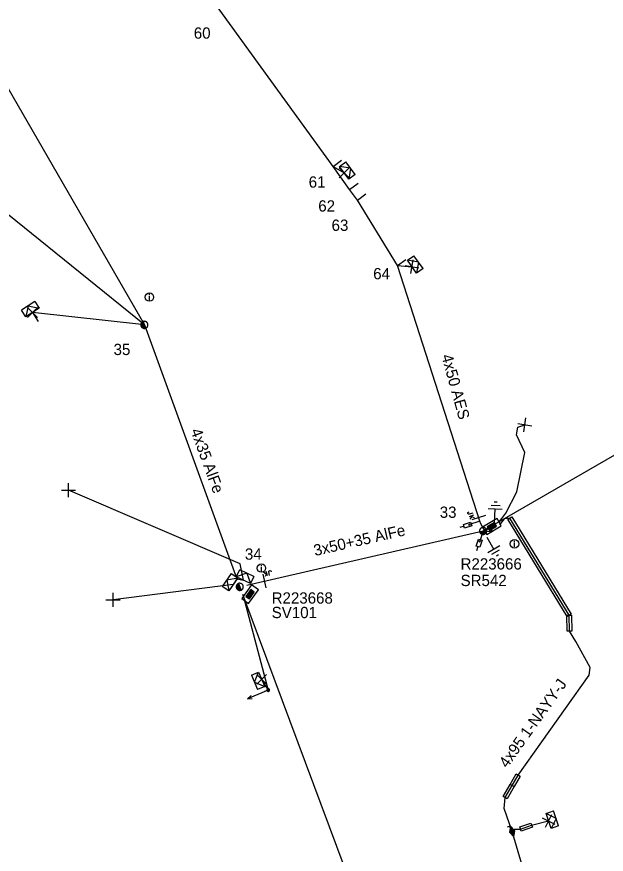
# Model space of a CAD drawing. Extents: x -536149 to -535465, y -1201639 to -1201298.
# Drawn here: x -535581.6 to -535529.3, y -1201567.7 to -1201493.4 of the extents above; entities that cross this region are included whole.
import ezdxf

# ---------------------------------------------------------------- set-up
doc = ezdxf.new("R2010")
doc.units = 0
for name, color, linetype in [('Vrstva 1', 7, 'Continuous'), ('Vrstva 10', 7, 'Continuous'), ('Vrstva 13', 7, 'Continuous'), ('Vrstva 14', 7, 'Continuous'), ('Vrstva 15', 7, 'Continuous'), ('Vrstva 16', 7, 'Continuous'), ('Vrstva 18', 7, 'Continuous'), ('Vrstva 19', 7, 'Continuous'), ('Vrstva 2', 7, 'Continuous'), ('Vrstva 20', 7, 'Continuous'), ('Vrstva 28', 7, 'Continuous'), ('Vrstva 29', 7, 'Continuous'), ('Vrstva 30', 7, 'Continuous'), ('Vrstva 31', 7, 'Continuous'), ('Vrstva 34', 7, 'Continuous'), ('Vrstva 36', 7, 'Continuous'), ('Vrstva 4', 7, 'Continuous'), ('Vrstva 5', 7, 'Continuous'), ('Vrstva 50', 7, 'Continuous'), ('Vrstva 51', 7, 'Continuous'), ('Vrstva 52', 7, 'Continuous'), ('Vrstva 54', 7, 'Continuous'), ('Vrstva 59', 7, 'Continuous'), ('Vrstva 6', 7, 'Continuous'), ('Vrstva 8', 7, 'Continuous'), ('Vrstva 9', 7, 'Continuous')]:
    doc.layers.add(name, color=color, linetype=linetype)

# ---------------------------------------------------------------- blocks, each defined once
blk = doc.blocks.new('NN440')
at = {"layer": 'Vrstva 2'}
for points in [[(0.63, 0), (0.63, 0.06), (0.62, 0.13), (0.6, 0.19), (0.58, 0.25), (0.55, 0.31), (0.51, 0.37), (0.47, 0.42), (0.42, 0.46), (0.37, 0.51), (0.32, 0.54), (0.26, 0.57), (0.2, 0.59), (0.13, 0.61), (0.07, 0.62), (0, 0.63), (-0.06, 0.62), (-0.13, 0.61), (-0.19, 0.59), (-0.26, 0.57), (-0.31, 0.54), (-0.37, 0.51), (-0.42, 0.46), (-0.47, 0.42), (-0.51, 0.37), (-0.54, 0.31), (-0.57, 0.25), (-0.6, 0.19), (-0.62, 0.13), (-0.63, 0.06), (-0.63, 0), (-0.63, -0.07), (-0.62, -0.14), (-0.6, -0.2), (-0.57, -0.26), (-0.54, -0.32), (-0.51, -0.37), (-0.47, -0.43), (-0.42, -0.47), (-0.37, -0.51), (-0.31, -0.55), (-0.26, -0.58), (-0.19, -0.6), (-0.13, -0.62), (-0.06, -0.63), (0, -0.63), (0.07, -0.63), (0.13, -0.62), (0.2, -0.6), (0.26, -0.58), (0.32, -0.55), (0.37, -0.51), (0.42, -0.47), (0.47, -0.43), (0.51, -0.37), (0.55, -0.32), (0.58, -0.26), (0.6, -0.2), (0.62, -0.14), (0.63, -0.07), (0.63, 0)], [(-0.63, 0), (0.63, 0)], [(-0.6, -0.18), (0.57, -0.18)], [(-0.51, -0.32), (0.5, -0.32)], [(-0.37, -0.47), (0.35, -0.47)]]:
    blk.add_lwpolyline(points, dxfattribs=at)
blk = doc.blocks.new('NN560')
at = {"layer": 'Vrstva 2'}
for points in [[(1.999, -0.001), (1.59, 0.141)], [(0, -0.001), (1.999, -0.001)], [(1.999, -0.001), (1.59, -0.134)]]:
    blk.add_lwpolyline(points, dxfattribs=at)
blk = doc.blocks.new('NN840')
at = {"layer": 'Vrstva 15'}
for points in [[(0.003, 0.619), (0.003, -0.631)], [(-0.745, -0.71), (-0.745, -0.66)], [(-0.73, -0.764), (-0.745, -0.71)], [(-0.538, -0.71), (-0.558, -0.764)], [(-0.538, -0.385), (-0.538, -0.71)], [(-0.332, -0.385), (-0.332, -0.798)], [(-0.332, -0.641), (-0.125, -0.385)], [(-0.263, -0.557), (-0.091, -0.798)], [(-0.657, -0.798), (-0.73, -0.764)], [(-0.627, -0.798), (-0.657, -0.798)], [(-0.558, -0.764), (-0.627, -0.798)]]:
    blk.add_lwpolyline(points, dxfattribs=at)
blk = doc.blocks.new('NN770')
at = {"layer": 'Vrstva 10'}
for p, q in [((0.002, 0.187), (0.002, 0.263)), ((0.002, -0.276), (0.002, 0.111))]:
    blk.add_line(p, q, dxfattribs=at)
blk.add_circle((0, -0.008), 0.375, dxfattribs=at)
blk = doc.blocks.new('NN880')
at = {"layer": 'Vrstva 4'}
for points in [[(0.001, 0.248), (-0.499, 0)], [(0.001, 0.185), (-0.373, 0)], [(0.001, 0.122), (-0.247, 0)], [(0.001, 0.059), (-0.125, 0)], [(0.501, 0), (0.001, 0.248)], [(0.375, 0), (0.001, 0.185)], [(0.249, 0), (0.001, 0.122)], [(0.127, 0), (0.001, 0.059)], [(-0.566, -0.13), (-0.436, -0.13)], [(-0.499, 0), (0.001, -0.252)], [(-0.499, -0.13), (-0.499, -0.327)], [(-0.373, 0), (0.001, -0.189)], [(-0.247, 0), (0.001, -0.126)], [(-0.125, 0), (0.001, -0.063)], [(0.001, -0.252), (0.501, 0)], [(0.001, -0.189), (0.375, 0)], [(0.001, -0.126), (0.249, 0)], [(0.001, -0.063), (0.127, 0)]]:
    blk.add_lwpolyline(points, dxfattribs=at)
blk = doc.blocks.new('NN800')
at = {"layer": 'Vrstva 1'}
for points in [[(-0.442, 0.442), (0.442, -0.442)], [(-0.442, -0.442), (0.442, 0.442)]]:
    blk.add_lwpolyline(points, dxfattribs=at)
blk = doc.blocks.new('NN820')
at = {"layer": 'Vrstva 13'}
for points in [[(-0.003, 0.004), (-0.003, -1.049)], [(-0.165, -0.813), (0.165, -0.813)], [(-0.165, -1.473), (-0.165, -0.813)], [(0.165, -1.473), (-0.165, -1.473)], [(-0.003, -1.049), (-0.062, -0.926)], [(-0.003, -1.049), (0.057, -0.926)], [(-0.003, -1.473), (-0.003, -1.871)], [(0.165, -0.813), (0.165, -1.473)]]:
    blk.add_lwpolyline(points, dxfattribs=at)
blk = doc.blocks.new('NN620')
at = {"layer": 'Vrstva 8'}
for points in [[(0.752, 0.004), (-0.748, 0.004)], [(-0.748, 0.004), (-0.748, -0.746)], [(0.752, -0.746), (0.752, 0.004)], [(0.368, -0.18), (-0.376, -0.18)], [(-0.376, -0.18), (-0.376, -0.558)], [(-0.376, -0.558), (0.368, -0.558)], [(0.321, -0.227), (-0.329, -0.227)], [(-0.329, -0.227), (-0.329, -0.51)], [(-0.329, -0.51), (0.321, -0.51)], [(0.274, -0.274), (-0.281, -0.274)], [(-0.281, -0.274), (-0.281, -0.463)], [(-0.281, -0.463), (0.274, -0.463)], [(0.227, -0.321), (-0.234, -0.321)], [(-0.234, -0.321), (-0.234, -0.416)], [(-0.234, -0.416), (0.227, -0.416)], [(-0.193, -0.369), (0.185, -0.369)], [(0.227, -0.416), (0.227, -0.321)], [(0.274, -0.463), (0.274, -0.274)], [(0.321, -0.51), (0.321, -0.227)], [(0.368, -0.558), (0.368, -0.18)], [(-0.748, -0.746), (0.752, -0.746)]]:
    blk.add_lwpolyline(points, dxfattribs=at)
blk = doc.blocks.new('NN630')
at = {"layer": 'Vrstva 9'}
for points in [[(-0.003, -0.7), (-0.703, 0)], [(-0.703, -0.7), (-0.703, 0), (0.697, 0), (0.697, -0.7)], [(-0.703, -0.7), (0.697, -0.7)], [(-0.003, -0.7), (0.697, 0)]]:
    blk.add_lwpolyline(points, dxfattribs=at)
blk = doc.blocks.new('NN810')
at = {"layer": 'Vrstva 14'}
for points in [[(0.004, -0.64), (0.004, -1.89)], [(0.629, -1.89), (-0.621, -1.89)], [(0.388, -2.2), (-0.399, -2.2)], [(0.004, -2.515), (-0.124, -2.515)], [(0.137, -2.515), (0.004, -2.515)]]:
    blk.add_lwpolyline(points, dxfattribs=at)
blk = doc.blocks.new('NN500')
at = {"layer": 'Vrstva 2'}
for points in [[(0, -0.24), (0.02, -0.23), (0.05, -0.23), (0.07, -0.22), (0.09, -0.22), (0.12, -0.2), (0.14, -0.19), (0.16, -0.18), (0.17, -0.16), (0.19, -0.14), (0.2, -0.12), (0.21, -0.1), (0.22, -0.07), (0.23, -0.05), (0.23, -0.02), (0.23, 0), (0.23, 0.02), (0.23, 0.05), (0.22, 0.07), (0.21, 0.1), (0.2, 0.12), (0.19, 0.14), (0.17, 0.16), (0.16, 0.17), (0.14, 0.19), (0.12, 0.2), (0.09, 0.21), (0.07, 0.22), (0.05, 0.23), (0.02, 0.23), (0, 0.23), (-0.03, 0.23), (-0.05, 0.23), (-0.07, 0.22), (-0.1, 0.21), (-0.12, 0.2), (-0.14, 0.19), (-0.16, 0.17), (-0.18, 0.16), (-0.19, 0.14), (-0.2, 0.12), (-0.22, 0.1), (-0.22, 0.07), (-0.23, 0.05), (-0.23, 0.02), (-0.24, 0), (-0.23, -0.02), (-0.23, -0.05), (-0.22, -0.07), (-0.22, -0.1), (-0.2, -0.12), (-0.19, -0.14), (-0.18, -0.16), (-0.16, -0.18), (-0.14, -0.19), (-0.12, -0.2), (-0.1, -0.22), (-0.07, -0.22), (-0.05, -0.23), (-0.03, -0.23), (0, -0.24)], [(0, -0.24), (0.02, -0.23), (0.05, -0.23), (0.07, -0.22), (0.09, -0.22), (0.12, -0.2), (0.14, -0.19), (0.16, -0.18), (0.17, -0.16), (0.19, -0.14), (0.2, -0.12), (0.21, -0.1), (0.22, -0.07), (0.23, -0.05), (0.23, -0.02), (0.23, 0), (0.23, 0.02), (0.23, 0.05), (0.22, 0.07), (0.21, 0.1), (0.2, 0.12), (0.19, 0.14), (0.17, 0.16), (0.16, 0.17), (0.14, 0.19), (0.12, 0.2), (0.09, 0.21), (0.07, 0.22), (0.05, 0.23), (0.02, 0.23), (0, 0.23), (-0.03, 0.23), (-0.05, 0.23), (-0.07, 0.22), (-0.1, 0.21), (-0.12, 0.2), (-0.14, 0.19), (-0.16, 0.17), (-0.18, 0.16), (-0.19, 0.14), (-0.2, 0.12), (-0.22, 0.1), (-0.22, 0.07), (-0.23, 0.05), (-0.23, 0.02), (-0.24, 0), (-0.23, -0.02), (-0.23, -0.05), (-0.22, -0.07), (-0.22, -0.1), (-0.2, -0.12), (-0.19, -0.14), (-0.18, -0.16), (-0.16, -0.18), (-0.14, -0.19), (-0.12, -0.2), (-0.1, -0.22), (-0.07, -0.22), (-0.05, -0.23), (-0.03, -0.23), (0, -0.24)], [(0, -0.21), (0.02, -0.2), (0.04, -0.2), (0.06, -0.2), (0.08, -0.19), (0.1, -0.18), (0.12, -0.17), (0.14, -0.15), (0.15, -0.14), (0.16, -0.12), (0.18, -0.1), (0.19, -0.08), (0.19, -0.06), (0.2, -0.04), (0.2, -0.02), (0.2, 0), (0.2, 0.02), (0.2, 0.04), (0.19, 0.06), (0.19, 0.08), (0.18, 0.1), (0.16, 0.12), (0.15, 0.14), (0.14, 0.15), (0.12, 0.17), (0.1, 0.18), (0.08, 0.19), (0.06, 0.19), (0.04, 0.2), (0.02, 0.2), (0, 0.2), (-0.02, 0.2), (-0.04, 0.2), (-0.06, 0.19), (-0.08, 0.19), (-0.1, 0.18), (-0.12, 0.17), (-0.14, 0.15), (-0.15, 0.14), (-0.17, 0.12), (-0.18, 0.1), (-0.19, 0.08), (-0.2, 0.06), (-0.2, 0.04), (-0.21, 0.02), (-0.21, 0), (-0.21, -0.02), (-0.2, -0.04), (-0.2, -0.06), (-0.19, -0.08), (-0.18, -0.1), (-0.17, -0.12), (-0.15, -0.14), (-0.14, -0.15), (-0.12, -0.17), (-0.1, -0.18), (-0.08, -0.19), (-0.06, -0.2), (-0.04, -0.2), (-0.02, -0.2), (0, -0.21)], [(0, -0.18), (0.02, -0.18), (0.04, -0.17), (0.05, -0.17), (0.07, -0.16), (0.09, -0.15), (0.1, -0.14), (0.12, -0.13), (0.13, -0.12), (0.14, -0.1), (0.15, -0.09), (0.16, -0.07), (0.17, -0.05), (0.17, -0.04), (0.17, -0.02), (0.17, 0), (0.17, 0.02), (0.17, 0.04), (0.17, 0.05), (0.16, 0.07), (0.15, 0.09), (0.14, 0.1), (0.13, 0.12), (0.12, 0.13), (0.1, 0.14), (0.09, 0.15), (0.07, 0.16), (0.05, 0.17), (0.04, 0.17), (0.02, 0.17), (0, 0.18), (-0.02, 0.17), (-0.04, 0.17), (-0.06, 0.17), (-0.07, 0.16), (-0.09, 0.15), (-0.1, 0.14), (-0.12, 0.13), (-0.13, 0.12), (-0.14, 0.1), (-0.15, 0.09), (-0.16, 0.07), (-0.17, 0.05), (-0.17, 0.04), (-0.18, 0.02), (-0.18, 0), (-0.18, -0.02), (-0.17, -0.04), (-0.17, -0.05), (-0.16, -0.07), (-0.15, -0.09), (-0.14, -0.1), (-0.13, -0.12), (-0.12, -0.13), (-0.1, -0.14), (-0.09, -0.15), (-0.07, -0.16), (-0.06, -0.17), (-0.04, -0.17), (-0.02, -0.18), (0, -0.18)], [(0, -0.15), (0.01, -0.15), (0.03, -0.14), (0.04, -0.14), (0.06, -0.13), (0.07, -0.13), (0.08, -0.12), (0.1, -0.11), (0.11, -0.1), (0.12, -0.09), (0.13, -0.07), (0.13, -0.06), (0.14, -0.05), (0.14, -0.03), (0.14, -0.02), (0.14, 0), (0.14, 0.01), (0.14, 0.03), (0.14, 0.04), (0.13, 0.06), (0.13, 0.07), (0.12, 0.09), (0.11, 0.1), (0.1, 0.11), (0.08, 0.12), (0.07, 0.13), (0.06, 0.13), (0.04, 0.14), (0.03, 0.14), (0.01, 0.14), (0, 0.15), (-0.02, 0.14), (-0.03, 0.14), (-0.05, 0.14), (-0.06, 0.13), (-0.07, 0.13), (-0.09, 0.12), (-0.1, 0.11), (-0.11, 0.1), (-0.12, 0.09), (-0.13, 0.07), (-0.13, 0.06), (-0.14, 0.04), (-0.14, 0.03), (-0.15, 0.01), (-0.15, 0), (-0.15, -0.02), (-0.14, -0.03), (-0.14, -0.05), (-0.13, -0.06), (-0.13, -0.07), (-0.12, -0.09), (-0.11, -0.1), (-0.1, -0.11), (-0.09, -0.12), (-0.07, -0.13), (-0.06, -0.13), (-0.05, -0.14), (-0.03, -0.14), (-0.02, -0.15), (0, -0.15)], [(0, -0.12), (0.01, -0.12), (0.02, -0.11), (0.03, -0.11), (0.05, -0.11), (0.06, -0.1), (0.07, -0.09), (0.08, -0.09), (0.09, -0.08), (0.09, -0.07), (0.1, -0.06), (0.11, -0.05), (0.11, -0.04), (0.11, -0.02), (0.11, -0.01), (0.12, 0), (0.11, 0.01), (0.11, 0.02), (0.11, 0.04), (0.11, 0.05), (0.1, 0.06), (0.09, 0.07), (0.09, 0.08), (0.08, 0.09), (0.07, 0.09), (0.06, 0.1), (0.05, 0.11), (0.03, 0.11), (0.02, 0.11), (0.01, 0.12), (0, 0.12), (-0.01, 0.12), (-0.03, 0.11), (-0.04, 0.11), (-0.05, 0.11), (-0.06, 0.1), (-0.07, 0.09), (-0.08, 0.09), (-0.09, 0.08), (-0.1, 0.07), (-0.1, 0.06), (-0.11, 0.05), (-0.11, 0.04), (-0.12, 0.02), (-0.12, 0.01), (-0.12, 0), (-0.12, -0.01), (-0.12, -0.02), (-0.11, -0.04), (-0.11, -0.05), (-0.1, -0.06), (-0.1, -0.07), (-0.09, -0.08), (-0.08, -0.09), (-0.07, -0.09), (-0.06, -0.1), (-0.05, -0.11), (-0.04, -0.11), (-0.03, -0.11), (-0.01, -0.12), (0, -0.12)], [(0, -0.09), (0.01, -0.09), (0.02, -0.09), (0.03, -0.08), (0.03, -0.08), (0.04, -0.08), (0.05, -0.07), (0.06, -0.07), (0.06, -0.06), (0.07, -0.05), (0.07, -0.04), (0.08, -0.04), (0.08, -0.03), (0.08, -0.02), (0.09, -0.01), (0.09, 0), (0.09, 0.01), (0.08, 0.02), (0.08, 0.03), (0.08, 0.03), (0.07, 0.04), (0.07, 0.05), (0.06, 0.06), (0.06, 0.06), (0.05, 0.07), (0.04, 0.07), (0.03, 0.08), (0.03, 0.08), (0.02, 0.08), (0.01, 0.09), (0, 0.09), (-0.01, 0.09), (-0.02, 0.08), (-0.03, 0.08), (-0.04, 0.08), (-0.04, 0.07), (-0.05, 0.07), (-0.06, 0.06), (-0.07, 0.06), (-0.07, 0.05), (-0.08, 0.04), (-0.08, 0.03), (-0.08, 0.03), (-0.09, 0.02), (-0.09, 0.01), (-0.09, 0), (-0.09, -0.01), (-0.09, -0.02), (-0.08, -0.03), (-0.08, -0.04), (-0.08, -0.04), (-0.07, -0.05), (-0.07, -0.06), (-0.06, -0.07), (-0.05, -0.07), (-0.04, -0.08), (-0.04, -0.08), (-0.03, -0.08), (-0.02, -0.09), (-0.01, -0.09), (0, -0.09)], [(0, -0.06), (0, -0.06), (0.01, -0.06), (0.02, -0.05), (0.02, -0.05), (0.03, -0.05), (0.03, -0.05), (0.04, -0.04), (0.04, -0.04), (0.05, -0.03), (0.05, -0.03), (0.05, -0.02), (0.05, -0.02), (0.05, -0.01), (0.06, -0.01), (0.06, 0), (0.06, 0.01), (0.05, 0.01), (0.05, 0.02), (0.05, 0.02), (0.05, 0.03), (0.05, 0.03), (0.04, 0.04), (0.04, 0.04), (0.03, 0.05), (0.03, 0.05), (0.02, 0.05), (0.02, 0.05), (0.01, 0.06), (0, 0.06), (0, 0.06), (-0.01, 0.06), (-0.01, 0.06), (-0.02, 0.05), (-0.02, 0.05), (-0.03, 0.05), (-0.03, 0.05), (-0.04, 0.04), (-0.04, 0.04), (-0.05, 0.03), (-0.05, 0.03), (-0.05, 0.02), (-0.06, 0.02), (-0.06, 0.01), (-0.06, 0.01), (-0.06, 0), (-0.06, -0.01), (-0.06, -0.01), (-0.06, -0.02), (-0.05, -0.02), (-0.05, -0.03), (-0.05, -0.03), (-0.04, -0.04), (-0.04, -0.04), (-0.03, -0.05), (-0.03, -0.05), (-0.02, -0.05), (-0.02, -0.05), (-0.01, -0.06), (-0.01, -0.06), (0, -0.06)], [(0, -0.03), (0, -0.03), (0, -0.03), (0.01, -0.03), (0.01, -0.03), (0.01, -0.02), (0.02, -0.02), (0.02, -0.02), (0.02, -0.02), (0.02, -0.02), (0.02, -0.01), (0.02, -0.01), (0.03, -0.01), (0.03, -0.01), (0.03, 0), (0.03, 0), (0.03, 0), (0.03, 0.01), (0.03, 0.01), (0.02, 0.01), (0.02, 0.01), (0.02, 0.02), (0.02, 0.02), (0.02, 0.02), (0.02, 0.02), (0.01, 0.02), (0.01, 0.02), (0.01, 0.03), (0, 0.03), (0, 0.03), (0, 0.03), (0, 0.03), (-0.01, 0.03), (-0.01, 0.03), (-0.01, 0.02), (-0.02, 0.02), (-0.02, 0.02), (-0.02, 0.02), (-0.02, 0.02), (-0.02, 0.02), (-0.03, 0.01), (-0.03, 0.01), (-0.03, 0.01), (-0.03, 0.01), (-0.03, 0), (-0.03, 0), (-0.03, 0), (-0.03, -0.01), (-0.03, -0.01), (-0.03, -0.01), (-0.03, -0.01), (-0.02, -0.02), (-0.02, -0.02), (-0.02, -0.02), (-0.02, -0.02), (-0.02, -0.02), (-0.01, -0.03), (-0.01, -0.03), (-0.01, -0.03), (0, -0.03), (0, -0.03)], [(0.23, 0), (0.7, 0)]]:
    blk.add_lwpolyline(points, dxfattribs=at)
blk = doc.blocks.new('NN510')
at = {"layer": 'Vrstva 2'}
blk.add_lwpolyline([(0.001, 0.002), (0.001, 0.939)], dxfattribs=at)

msp = doc.modelspace()

# ---------------------------------------------------------------- linework, layer by layer
at = {"layer": 'Vrstva 1'}
for points in [[(-535704.28, -1201335.78), (-535687.29, -1201370.27), (-535663.05, -1201399.63), (-535635.32, -1201433.41), (-535614.862, -1201457.774), (-535589.24, -1201487.744), (-535570.255, -1201520.699), (-535562.055, -1201543.241)], [(-535540.23, -1201538.98), (-535514.019, -1201523.838), (-535479.236, -1201502.472), (-535465.278, -1201493.607)], [(-535561.176, -1201543.795), (-535540.23, -1201538.98)], [(-535540.143, -1201611.931), (-535549.68, -1201576.4), (-535561.545, -1201544.626)]]:
    msp.add_lwpolyline(points, dxfattribs=at)
at = {"layer": 'Vrstva 20'}
for points in [[(-535537.689, -1201537.736), (-535532.439, -1201546.356), (-535532.781, -1201546.564), (-535538.031, -1201537.944)], [(-535532.41, -1201546.456), (-535532.38, -1201547.866), (-535532.78, -1201547.874), (-535532.81, -1201546.464)], [(-535536.947, -1201560.74), (-535537.487, -1201561.67), (-535537.833, -1201561.47), (-535537.293, -1201560.54)], [(-535538.453, -1201562.54), (-535537.833, -1201561.47), (-535537.487, -1201561.67), (-535538.107, -1201562.74)], [(-535536.985, -1201565.241), (-535535.995, -1201564.901), (-535535.865, -1201565.279), (-535536.855, -1201565.619)]]:
    msp.add_lwpolyline(points, close=True, dxfattribs=at)
at = {"layer": 'Vrstva 5'}
for points in [[(-535535.21, -1201573.95), (-535537.66, -1201565.65), (-535538.38, -1201563.6), (-535538.28, -1201562.64), (-535537.66, -1201561.57), (-535537.12, -1201560.64), (-535530.83, -1201551.78), (-535530.75, -1201551.1), (-535532.02, -1201548.79), (-535532.58, -1201547.87), (-535532.61, -1201546.46), (-535537.86, -1201537.84), (-535538.354, -1201537.917), (-535538.774, -1201538.446)], [(-535539.437, -1201538.974), (-535539.525, -1201538.828), (-535540.129, -1201538.872), (-535540.439, -1201538.364)], [(-535539.505, -1201539.027), (-535540.173, -1201539.076), (-535540.23, -1201538.98)]]:
    msp.add_lwpolyline(points, dxfattribs=at)
at = {"layer": 'Vrstva 50'}
msp.add_lwpolyline([(-535540.439, -1201538.364), (-535540.519, -1201538.116), (-535547.83, -1201515.436), (-535551.375, -1201509.636), (-535552.066, -1201508.681), (-535553.538, -1201506.643), (-535563.322, -1201493.118), (-535566.21, -1201489.133)], dxfattribs=at)
at = {"layer": 'Vrstva 52'}
for points in [[(-535538.872, -1201538.248), (-535538.578, -1201537.878), (-535538.228, -1201537.41), (-535537.25, -1201535.5), (-535536.54, -1201532.03), (-535537.27, -1201530.46), (-535537.16, -1201529.79), (-535536.53, -1201529.56)], [(-535537.66, -1201565.65), (-535537.48, -1201565.45), (-535536.92, -1201565.43), (-535535.93, -1201565.09), (-535534.43, -1201564.71)]]:
    msp.add_lwpolyline(points, dxfattribs=at)
at = {"layer": 'Vrstva 54'}
for points in [[(-535570.255, -1201520.699), (-535587.383, -1201506.844)], [(-535547.831, -1201515.436), (-535546.538, -1201515.538)], [(-535570.255, -1201520.699), (-535580.184, -1201519.608)], [(-535562.054, -1201543.241), (-535562.382, -1201543.723)], [(-535562.055, -1201543.241), (-535561.477, -1201543.362)], [(-535561.545, -1201544.626), (-535559.28, -1201553.1), (-535559.861, -1201552.148)]]:
    msp.add_lwpolyline(points, dxfattribs=at)
at = {"layer": 'Vrstva 59'}
for points in [[(-535561.477, -1201543.362), (-535561.769, -1201541.904), (-535576.978, -1201535.361)], [(-535562.382, -1201543.723), (-535573.038, -1201545.098)]]:
    msp.add_lwpolyline(points, dxfattribs=at)
at = {"layer": 'Vrstva 8'}
msp.add_lwpolyline([(-535553.538, -1201506.643), (-535552.546, -1201507.204)], dxfattribs=at)

# ---------------------------------------------------------------- block references
at = {"layer": 'Vrstva 13'}
for name, p, rotation in [('NN510', (-535553.539, -1201506.643), -54.1297111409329), ('NN510', (-535552.067, -1201508.681), -54.14577773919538), ('NN510', (-535551.376, -1201509.636), -54.15740823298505), ('NN510', (-535547.832, -1201515.436), -54.16792219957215), ('NN510', (-535580.183, -1201519.607), -146.90289160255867), ('NN560', (-535559.28, -1201553.1), -157.3463943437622)]:
    msp.add_blockref(name, p, dxfattribs=dict(at, rotation=rotation))
for name, p, xscale, yscale, rotation in [('NN440', (-535570.255, -1201520.699), 0.5, 0.5000000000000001, -70.02306397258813), ('NN440', (-535540.23, -1201538.98), 0.5000000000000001, 0.4999999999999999, 29.96083386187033), ('NN440', (-535561.8, -1201543.94), 0.5000000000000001, 0.5, -69.56942776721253), ('NN500', (-535559.28, -1201553.1), 0.49999999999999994, 0.5000000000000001, -157.36799995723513)]:
    msp.add_blockref(name, p, dxfattribs=dict(at, xscale=xscale, yscale=yscale, rotation=rotation))
at = {"layer": 'Vrstva 15'}
for p, rotation in [((-535539.27, -1201538.91), 176.4442276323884), ((-535540.23, -1201538.98), 29.96083386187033)]:
    msp.add_blockref('NN810', p, dxfattribs=dict(at, rotation=rotation))
at = {"layer": 'Vrstva 16'}
for p, rotation in [((-535540.519, -1201538.116), -72.13095968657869), ((-535540.23, -1201538.98), -18.24602869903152)]:
    msp.add_blockref('NN820', p, dxfattribs=dict(at, rotation=rotation))
at = {"layer": 'Vrstva 18'}
for p, rotation in [((-535540.622, -1201537.795), -72.13095977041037), ((-535559.594, -1201543.428), -166.92921039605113)]:
    msp.add_blockref('NN840', p, dxfattribs=dict(at, rotation=rotation))
at = {"layer": 'Vrstva 19', "rotation": -73.5544154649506}
msp.add_blockref('NN880', (-535537.66, -1201565.65), dxfattribs=at)
at = {"layer": 'Vrstva 28'}
for p, rotation in [((-535539.27, -1201538.91), -149.77816187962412), ((-535561.19, -1201544.377), 54.43099991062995)]:
    msp.add_blockref('NN620', p, dxfattribs=dict(at, rotation=rotation))
at = {"layer": 'Vrstva 31'}
for p, rotation in [((-535552.546, -1201507.204), 125.85844165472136), ((-535546.538, -1201515.537), 125.86110827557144), ((-535580.184, -1201519.608), -146.90289173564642), ((-535562.382, -1201543.723), -124.23520557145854), ((-535561.476, -1201543.363), 154.93494158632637), ((-535559.861, -1201552.148), -67.39208054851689), ((-535534.43, -1201564.71), 108.5283246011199)]:
    msp.add_blockref('NN630', p, dxfattribs=dict(at, rotation=rotation))
at = {"layer": 'Vrstva 34'}
for p in [(-535552.546, -1201507.204), (-535580.184, -1201519.608), (-535559.861, -1201552.148)]:
    msp.add_blockref('NN800', p, dxfattribs=at)
for p, rotation in [((-535546.538, -1201515.538), 36.23112518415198), ((-535536.53, -1201529.56), 36.095597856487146), ((-535576.978, -1201535.362), 44.999999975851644), ((-535573.038, -1201545.098), 45), ((-535534.43, -1201564.71), 18.117972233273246)]:
    msp.add_blockref('NN800', p, dxfattribs=dict(at, rotation=rotation))
at = {"layer": 'Vrstva 36'}
for p in [(-535569.815, -1201518.224), (-535537.453, -1201540.122), (-535559.885, -1201542.269)]:
    msp.add_blockref('NN770', p, dxfattribs=at)

# ---------------------------------------------------------------- texts
at = {"layer": 'Vrstva 14'}
for s, p in [('60', (-535565.878, -1201495.308)), ('61', (-535555.694, -1201508.522)), ('62', (-535554.844, -1201510.648)), ('63', (-535553.665, -1201512.36)), ('64', (-535549.975, -1201516.654)), ('35', (-535572.989, -1201523.379)), ('33', (-535544.077, -1201537.821)), ('34', (-535561.347, -1201541.534))]:
    msp.add_text(s, height=1, dxfattribs=at).set_placement(p)
at = {"layer": 'Vrstva 2'}
for s, rotation, p in [('4x35 AlFe', 289.977, (-535566.176, -1201530.086)), ('3x50+35 AlFe', 12.946, (-535555.132, -1201541.217))]:
    msp.add_text(s, height=1, rotation=rotation, dxfattribs=at).set_placement(p)
at = {"layer": 'Vrstva 29'}
for s, p in [('R223666', (-535542.234, -1201542.408)), ('R223668', (-535558.98, -1201545.43))]:
    msp.add_text(s, height=1, dxfattribs=at).set_placement(p)
at = {"layer": 'Vrstva 30'}
for s, p in [('SR542', (-535542.23, -1201543.876)), ('SV101', (-535558.973, -1201546.718))]:
    msp.add_text(s, height=1, dxfattribs=at).set_placement(p)
at = {"layer": 'Vrstva 51'}
msp.add_text('4x50 AES', height=1, rotation=285.401, dxfattribs=at).set_placement((-535543.936, -1201523.451))
at = {"layer": 'Vrstva 6'}
msp.add_text('4x95 1-NAYY-J', height=1, rotation=54.628, dxfattribs=at).set_placement((-535538.096, -1201560.083))

doc.saveas('drawing.dxf')
